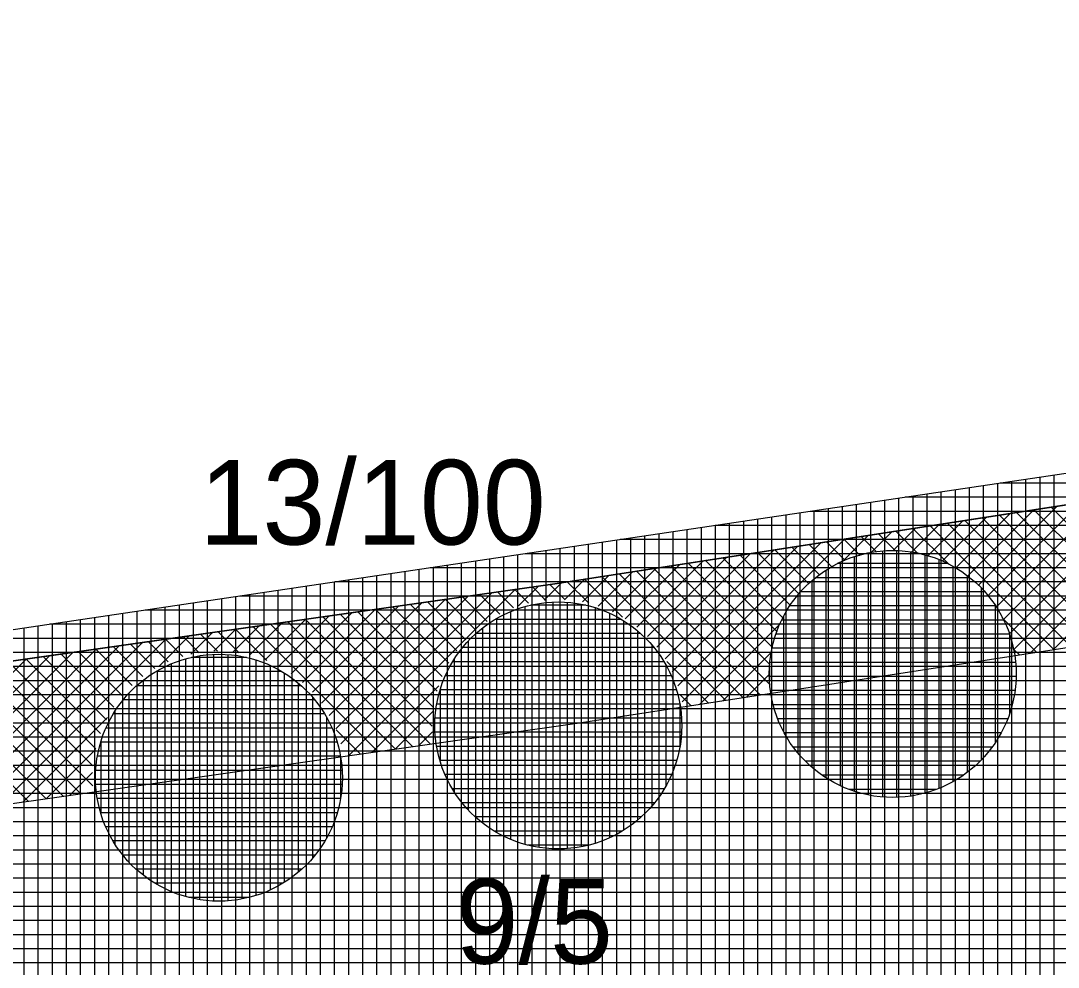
# Model space of a CAD drawing. Extents: x -565346 to -564154, y -1097386 to -1095620.
# Drawn here: x -564969.31 to -564954.61, y -1095806.24 to -1095792.83 of the extents above; entities that cross this region are included whole.
import ezdxf

# ---------------------------------------------------------------- set-up
doc = ezdxf.new("R2010")
doc.units = 0
for name, color, linetype in [('Vrstva 13', 7, 'Continuous'), ('Vrstva 40', 7, 'Continuous'), ('Vrstva 41', 7, 'Continuous'), ('Vrstva 42', 7, 'Continuous'), ('Vrstva 43', 7, 'Continuous'), ('Vrstva 44', 7, 'Continuous')]:
    doc.layers.add(name, color=color, linetype=linetype)

msp = doc.modelspace()

# ---------------------------------------------------------------- linework, layer by layer
at = {"layer": 'Vrstva 13'}
for p, q in [((-564961.71, -1095800.8), (-564879.81, -1095788.15)), ((-565039.47, -1095811.86), (-564961.71, -1095800.8))]:
    msp.add_line(p, q, dxfattribs=at)
at = {"layer": 'Vrstva 41'}
for p, q in [((-564955.303, -1095801.518), (-564953.283, -1095799.498)), ((-564955.243, -1095801.741), (-564952.948, -1095799.447)), ((-564955.608, -1095800.975), (-564954.286, -1095799.653)), ((-564955.489, -1095801.139), (-564953.952, -1095799.602)), ((-564955.387, -1095801.319), (-564953.617, -1095799.55)), ((-564956.064, -1095800.583), (-564955.29, -1095799.808)), ((-564955.896, -1095800.697), (-564954.955, -1095799.757)), ((-564955.744, -1095800.828), (-564954.621, -1095799.705)), ((-564953.995, -1095800.997), (-564955.197, -1095799.794)), ((-564953.933, -1095800.776), (-564954.952, -1095799.756)), ((-564953.849, -1095800.576), (-564954.707, -1095799.718)), ((-564956.691, -1095800.361), (-564956.293, -1095799.963)), ((-564956.458, -1095800.411), (-564955.959, -1095799.912)), ((-564956.251, -1095800.486), (-564955.624, -1095799.86)), ((-564954.424, -1095801.698), (-564956.177, -1095799.945)), ((-564954.179, -1095801.661), (-564955.932, -1095799.908)), ((-564954.022, -1095801.535), (-564955.687, -1095799.87)), ((-564954.026, -1095801.248), (-564955.442, -1095799.832)), ((-564957.671, -1095800.493), (-564957.297, -1095800.118)), ((-564957.263, -1095800.368), (-564956.962, -1095800.067)), ((-564956.914, -1095800.34), (-564957.157, -1095800.097)), ((-564956.951, -1095800.338), (-564956.628, -1095800.015)), ((-564956.596, -1095800.375), (-564956.912, -1095800.059)), ((-564956.153, -1095800.535), (-564956.667, -1095800.021)), ((-564954.669, -1095801.736), (-564956.422, -1095799.983)), ((-564959.998, -1095802.254), (-564957.966, -1095800.222)), ((-564959.94, -1095802.479), (-564957.631, -1095800.17)), ((-564957.818, -1095800.567), (-564958.137, -1095800.248)), ((-564957.628, -1095800.475), (-564957.892, -1095800.21)), ((-564957.417, -1095800.403), (-564957.647, -1095800.172)), ((-564957.182, -1095800.355), (-564957.402, -1095800.135)), ((-564960.297, -1095801.704), (-564958.97, -1095800.377)), ((-564960.18, -1095801.87), (-564958.635, -1095800.325)), ((-564960.08, -1095802.053), (-564958.3, -1095800.273)), ((-564958.403, -1095801.114), (-564959.117, -1095800.4)), ((-564958.281, -1095800.952), (-564958.872, -1095800.362)), ((-564958.144, -1095800.808), (-564958.627, -1095800.324)), ((-564957.99, -1095800.679), (-564958.382, -1095800.286)), ((-564960.745, -1095801.303), (-564959.973, -1095800.532)), ((-564960.579, -1095801.421), (-564959.639, -1095800.48)), ((-564960.43, -1095801.554), (-564959.304, -1095800.428)), ((-564958.693, -1095801.955), (-564960.097, -1095800.551)), ((-564958.658, -1095801.707), (-564959.852, -1095800.513)), ((-564958.594, -1095801.489), (-564959.607, -1095800.475)), ((-564958.507, -1095801.292), (-564959.362, -1095800.437)), ((-564961.351, -1095801.061), (-564960.977, -1095800.687)), ((-564961.128, -1095801.121), (-564960.642, -1095800.635)), ((-564959.324, -1095802.455), (-564961.077, -1095800.702)), ((-564960.927, -1095801.203), (-564960.308, -1095800.583)), ((-564959.079, -1095802.417), (-564960.832, -1095800.664)), ((-564958.834, -1095802.379), (-564960.587, -1095800.627)), ((-564958.692, -1095802.239), (-564960.342, -1095800.589)), ((-564955.007, -1095801.788), (-564953.895, -1095800.676)), ((-564962.258, -1095801.12), (-564961.976, -1095800.838)), ((-564961.874, -1095801.037), (-564962.061, -1095800.85)), ((-564961.895, -1095801.039), (-564961.646, -1095800.79)), ((-564961.596, -1095801.032), (-564961.813, -1095800.815)), ((-564961.604, -1095801.032), (-564961.311, -1095800.738)), ((-564961.263, -1095801.082), (-564961.567, -1095800.778)), ((-564960.785, -1095801.277), (-564961.322, -1095800.74)), ((-564964.849, -1095802.862), (-564962.965, -1095800.979)), ((-564964.777, -1095803.073), (-564962.636, -1095800.932)), ((-564964.661, -1095803.24), (-564962.306, -1095800.885)), ((-564962.702, -1095801.341), (-564963.051, -1095800.991)), ((-564962.524, -1095801.235), (-564962.804, -1095800.956)), ((-564962.33, -1095801.147), (-564962.556, -1095800.92)), ((-564962.115, -1095801.079), (-564962.309, -1095800.885)), ((-564965.179, -1095802.344), (-564963.955, -1095801.119)), ((-564965.051, -1095802.499), (-564963.625, -1095801.072)), ((-564964.941, -1095802.671), (-564963.295, -1095801.025)), ((-564963.245, -1095801.929), (-564964.042, -1095801.132)), ((-564963.134, -1095801.757), (-564963.794, -1095801.096)), ((-564963.006, -1095801.602), (-564963.547, -1095801.061)), ((-564962.862, -1095801.463), (-564963.299, -1095801.026)), ((-564954.673, -1095801.737), (-564954.006, -1095801.07)), ((-564965.657, -1095801.973), (-564964.944, -1095801.26)), ((-564965.481, -1095802.08), (-564964.614, -1095801.213)), ((-564965.322, -1095802.204), (-564964.284, -1095801.166)), ((-564963.48, -1095802.825), (-564965.032, -1095801.273)), ((-564963.461, -1095802.561), (-564964.785, -1095801.237)), ((-564963.411, -1095802.328), (-564964.537, -1095801.202)), ((-564963.338, -1095802.118), (-564964.29, -1095801.167)), ((-564954.914, -1095801.774), (-564955.405, -1095801.283)), ((-564966.578, -1095801.763), (-564966.263, -1095801.448)), ((-564966.303, -1095801.77), (-564965.933, -1095801.401)), ((-564966.065, -1095801.815), (-564965.603, -1095801.354)), ((-564964.254, -1095803.182), (-564966.023, -1095801.413)), ((-564965.851, -1095801.884), (-564965.274, -1095801.307)), ((-564964.007, -1095803.147), (-564965.775, -1095801.378)), ((-564963.759, -1095803.112), (-564965.528, -1095801.343)), ((-564963.511, -1095803.076), (-564965.28, -1095801.308)), ((-564959.69, -1095802.512), (-564958.545, -1095801.367)), ((-564969.607, -1095803.943), (-564967.252, -1095801.588)), ((-564967.358, -1095801.976), (-564966.922, -1095801.541)), ((-564967.016, -1095801.835), (-564967.261, -1095801.59)), ((-564966.785, -1095801.783), (-564967.013, -1095801.554)), ((-564966.903, -1095801.805), (-564966.593, -1095801.494)), ((-564966.525, -1095801.76), (-564966.766, -1095801.519)), ((-564966.218, -1095801.784), (-564966.518, -1095801.484)), ((-564965.825, -1095801.894), (-564966.271, -1095801.449)), ((-564969.908, -1095803.396), (-564968.241, -1095801.729)), ((-564969.82, -1095803.59), (-564967.912, -1095801.682)), ((-564969.752, -1095803.806), (-564967.582, -1095801.635)), ((-564967.733, -1095802.248), (-564968.252, -1095801.73)), ((-564967.581, -1095802.119), (-564968.004, -1095801.695)), ((-564967.411, -1095802.005), (-564967.756, -1095801.66)), ((-564967.223, -1095801.91), (-564967.509, -1095801.625)), ((-564955.159, -1095801.812), (-564955.245, -1095801.726)), ((-564970.279, -1095802.918), (-564969.231, -1095801.87)), ((-564970.139, -1095803.061), (-564968.901, -1095801.823)), ((-564970.015, -1095803.22), (-564968.571, -1095801.776)), ((-564968.185, -1095802.929), (-564969.242, -1095801.871)), ((-564968.098, -1095802.733), (-564968.994, -1095801.836)), ((-564967.993, -1095802.555), (-564968.747, -1095801.801)), ((-564967.871, -1095802.394), (-564968.499, -1095801.766)), ((-564959.356, -1095802.46), (-564958.67, -1095801.775)), ((-564968.464, -1095803.781), (-564970.232, -1095802.012)), ((-564968.294, -1095803.668), (-564969.985, -1095801.977)), ((-564968.291, -1095803.388), (-564969.737, -1095801.942)), ((-564968.251, -1095803.146), (-564969.49, -1095801.907)), ((-564959.569, -1095802.493), (-564960.157, -1095801.905)), ((-564969.207, -1095803.886), (-564970.975, -1095802.118)), ((-564968.959, -1095803.851), (-564970.728, -1095802.083)), ((-564968.712, -1095803.816), (-564970.48, -1095802.047)), ((-564959.021, -1095802.408), (-564958.7, -1095802.087)), ((-564964.331, -1095803.193), (-564963.388, -1095802.25)), ((-564959.814, -1095802.531), (-564959.962, -1095802.383)), ((-564958.687, -1095802.357), (-564958.677, -1095802.347)), ((-564964.002, -1095803.146), (-564963.469, -1095802.613)), ((-564969.278, -1095803.896), (-564968.082, -1095802.7)), ((-564964.502, -1095803.217), (-564964.844, -1095802.875)), ((-564963.672, -1095803.099), (-564963.476, -1095802.904)), ((-564968.948, -1095803.85), (-564968.253, -1095803.155)), ((-564968.618, -1095803.803), (-564968.295, -1095803.48)), ((-564968.288, -1095803.756), (-564968.288, -1095803.755))]:
    msp.add_line(p, q, dxfattribs=at)
at = {"layer": 'Vrstva 42'}
msp.add_lwpolyline([(-565024.871, -1095809.784), (-565024.921, -1095811.811), (-564961.428, -1095802.78), (-564933.86, -1095798.523), (-564934.165, -1095796.546), (-564961.71, -1095800.8)], close=True, dxfattribs=at)
at = {"layer": 'Vrstva 43'}
for p, q in [((-564955.47, -1095799.386), (-564955.47, -1095814.547)), ((-564858.814, -1095799.38), (-564955.431, -1095799.38)), ((-564955.27, -1095799.356), (-564955.27, -1095814.518)), ((-564955.07, -1095799.326), (-564955.07, -1095814.488)), ((-564954.87, -1095799.297), (-564954.87, -1095814.458)), ((-564954.67, -1095799.267), (-564954.67, -1095814.429)), ((-564956.47, -1095799.534), (-564956.47, -1095814.696)), ((-564956.27, -1095799.505), (-564956.27, -1095814.666)), ((-564956.07, -1095799.475), (-564956.07, -1095814.637)), ((-564955.87, -1095799.445), (-564955.87, -1095814.607)), ((-564955.67, -1095799.415), (-564955.67, -1095814.577)), ((-564957.47, -1095799.683), (-564957.47, -1095814.845)), ((-564957.27, -1095799.653), (-564957.27, -1095814.815)), ((-564957.07, -1095799.623), (-564957.07, -1095814.785)), ((-564956.87, -1095799.594), (-564956.87, -1095814.755)), ((-564859.856, -1095799.58), (-564956.778, -1095799.58)), ((-564956.67, -1095799.564), (-564956.67, -1095814.726)), ((-564958.27, -1095799.802), (-564958.27, -1095814.963)), ((-564860.898, -1095799.78), (-564958.125, -1095799.78)), ((-564958.07, -1095799.772), (-564958.07, -1095814.934)), ((-564957.87, -1095799.742), (-564957.87, -1095814.904)), ((-564957.67, -1095799.712), (-564957.67, -1095814.874)), ((-564959.27, -1095799.95), (-564959.27, -1095815.112)), ((-564959.07, -1095799.92), (-564959.07, -1095815.082)), ((-564958.87, -1095799.891), (-564958.87, -1095815.052)), ((-564958.67, -1095799.861), (-564958.67, -1095815.023)), ((-564958.47, -1095799.831), (-564958.47, -1095814.993)), ((-564960.27, -1095800.099), (-564960.27, -1095815.26)), ((-564960.07, -1095800.069), (-564960.07, -1095815.231)), ((-564959.87, -1095800.039), (-564959.87, -1095815.201)), ((-564959.67, -1095800.009), (-564959.67, -1095815.171)), ((-564861.94, -1095799.98), (-564959.472, -1095799.98)), ((-564959.47, -1095799.98), (-564959.47, -1095815.142)), ((-564961.27, -1095800.247), (-564961.27, -1095815.409)), ((-564961.07, -1095800.217), (-564961.07, -1095815.379)), ((-564960.87, -1095800.188), (-564960.87, -1095815.349)), ((-564862.982, -1095800.18), (-564960.818, -1095800.18)), ((-564960.67, -1095800.158), (-564960.67, -1095815.32)), ((-564960.47, -1095800.128), (-564960.47, -1095815.29)), ((-564962.27, -1095800.396), (-564962.27, -1095815.557)), ((-564864.024, -1095800.38), (-564962.165, -1095800.38)), ((-564962.07, -1095800.366), (-564962.07, -1095815.528)), ((-564961.87, -1095800.336), (-564961.87, -1095815.498)), ((-564961.67, -1095800.306), (-564961.67, -1095815.468)), ((-564961.47, -1095800.277), (-564961.47, -1095815.439)), ((-564963.27, -1095800.544), (-564963.27, -1095815.706)), ((-564963.07, -1095800.514), (-564963.07, -1095815.676)), ((-564962.87, -1095800.485), (-564962.87, -1095815.647)), ((-564962.67, -1095800.455), (-564962.67, -1095815.617)), ((-564962.47, -1095800.425), (-564962.47, -1095815.587)), ((-564964.27, -1095800.693), (-564964.27, -1095815.854)), ((-564964.07, -1095800.663), (-564964.07, -1095815.825)), ((-564963.87, -1095800.633), (-564963.87, -1095815.795)), ((-564963.67, -1095800.603), (-564963.67, -1095815.765)), ((-564865.066, -1095800.58), (-564963.512, -1095800.58)), ((-564963.47, -1095800.574), (-564963.47, -1095815.736)), ((-564965.27, -1095800.841), (-564965.27, -1095816.003)), ((-564965.07, -1095800.811), (-564965.07, -1095815.973)), ((-564964.87, -1095800.782), (-564964.87, -1095815.944)), ((-564866.109, -1095800.78), (-564964.859, -1095800.78)), ((-564964.67, -1095800.752), (-564964.67, -1095815.914)), ((-564964.47, -1095800.722), (-564964.47, -1095815.884)), ((-564966.27, -1095800.99), (-564966.27, -1095816.152)), ((-564867.151, -1095800.98), (-564966.206, -1095800.98)), ((-564966.07, -1095800.96), (-564966.07, -1095816.122)), ((-564965.87, -1095800.93), (-564965.87, -1095816.092)), ((-564965.67, -1095800.9), (-564965.67, -1095816.062)), ((-564965.47, -1095800.871), (-564965.47, -1095816.033)), ((-564967.27, -1095801.138), (-564967.27, -1095816.3)), ((-564967.07, -1095801.108), (-564967.07, -1095816.27)), ((-564966.87, -1095801.079), (-564966.87, -1095816.241)), ((-564966.67, -1095801.049), (-564966.67, -1095816.211)), ((-564966.47, -1095801.019), (-564966.47, -1095816.181)), ((-564968.27, -1095801.287), (-564968.27, -1095816.449)), ((-564968.07, -1095801.257), (-564968.07, -1095816.419)), ((-564967.87, -1095801.227), (-564967.87, -1095816.389)), ((-564967.67, -1095801.197), (-564967.67, -1095816.359)), ((-564868.193, -1095801.18), (-564967.552, -1095801.18)), ((-564967.47, -1095801.168), (-564967.47, -1095816.33)), ((-564969.27, -1095801.435), (-564969.27, -1095816.597)), ((-564969.07, -1095801.405), (-564969.07, -1095816.567)), ((-564869.235, -1095801.38), (-564968.899, -1095801.38)), ((-564968.87, -1095801.376), (-564968.87, -1095816.538)), ((-564968.67, -1095801.346), (-564968.67, -1095816.508)), ((-564968.47, -1095801.316), (-564968.47, -1095816.478)), ((-564870.277, -1095801.58), (-564970.246, -1095801.58)), ((-564871.319, -1095801.78), (-564971.593, -1095801.78)), ((-564872.361, -1095801.98), (-564972.939, -1095801.98)), ((-564873.404, -1095802.18), (-564974.286, -1095802.18)), ((-564874.446, -1095802.38), (-564975.633, -1095802.38)), ((-564875.488, -1095802.58), (-564976.98, -1095802.58)), ((-564876.53, -1095802.78), (-564978.326, -1095802.78)), ((-564877.587, -1095802.98), (-564979.673, -1095802.98)), ((-564878.934, -1095803.18), (-564981.02, -1095803.18)), ((-564880.28, -1095803.38), (-564982.367, -1095803.38)), ((-564881.627, -1095803.58), (-564983.714, -1095803.58)), ((-564882.974, -1095803.78), (-564985.06, -1095803.78)), ((-564884.32, -1095803.98), (-564986.407, -1095803.98)), ((-564885.667, -1095804.18), (-564987.754, -1095804.18)), ((-564887.013, -1095804.38), (-564989.101, -1095804.38)), ((-564888.36, -1095804.58), (-564990.447, -1095804.58)), ((-564889.707, -1095804.78), (-564991.794, -1095804.78)), ((-564891.053, -1095804.98), (-564993.141, -1095804.98)), ((-564892.4, -1095805.18), (-564994.488, -1095805.18)), ((-564893.746, -1095805.38), (-564995.835, -1095805.38)), ((-564895.093, -1095805.58), (-564997.181, -1095805.58)), ((-564896.439, -1095805.78), (-564998.528, -1095805.78)), ((-564897.786, -1095805.98), (-564999.875, -1095805.98)), ((-564899.133, -1095806.18), (-565001.222, -1095806.18))]:
    msp.add_line(p, q, dxfattribs=at)
msp.add_lwpolyline([(-564584.17, -1095730.99), (-564361.01, -1095672.63), (-564329.81, -1095662.26), (-564326.21, -1095642.73), (-564394.52, -1095662.95), (-564454.33, -1095677.56), (-564516.6, -1095690.89), (-564574.04, -1095705.03), (-564590.74, -1095715.12), (-564631.48, -1095731.18), (-564693.31, -1095752.31), (-564772.2, -1095768.91), (-564879.81, -1095788.15), (-565039.47, -1095811.86), (-565040.85, -1095849.94), (-565025.81, -1095848.33), (-565025.24, -1095824.91), (-564877.52, -1095802.97), (-564694, -1095767.75), (-564603.8, -1095739.23), (-564594.74, -1095734.52)], close=True, dxfattribs=at)
at = {"layer": 'Vrstva 44'}
for p, q in [((-564957.3, -1095800.37), (-564957.3, -1095803.798)), ((-564957.1, -1095800.34), (-564957.1, -1095803.826)), ((-564956.9, -1095800.336), (-564956.9, -1095803.831)), ((-564956.7, -1095800.354), (-564956.7, -1095803.814)), ((-564956.5, -1095800.396), (-564956.5, -1095803.774)), ((-564956.173, -1095800.52), (-564957.739, -1095800.52)), ((-564957.7, -1095800.503), (-564957.7, -1095803.665)), ((-564957.5, -1095800.423), (-564957.5, -1095803.745)), ((-564956.3, -1095800.462), (-564956.3, -1095803.705)), ((-564956.1, -1095800.558), (-564956.1, -1095803.609)), ((-564957.9, -1095800.613), (-564957.9, -1095803.556)), ((-564955.9, -1095800.69), (-564955.9, -1095803.48)), ((-564958.1, -1095800.764), (-564958.1, -1095803.404)), ((-564955.859, -1095800.72), (-564958.048, -1095800.72)), ((-564958.3, -1095800.968), (-564958.3, -1095803.201)), ((-564955.65, -1095800.92), (-564958.261, -1095800.92)), ((-564955.7, -1095800.865), (-564955.7, -1095803.302)), ((-564962.17, -1095801.13), (-564962.17, -1095804.497)), ((-564961.302, -1095801.11), (-564962.084, -1095801.11)), ((-564961.97, -1095801.087), (-564961.97, -1095804.54)), ((-564961.77, -1095801.068), (-564961.77, -1095804.561)), ((-564961.57, -1095801.07), (-564961.57, -1095804.559)), ((-564961.37, -1095801.096), (-564961.37, -1095804.532)), ((-564961.17, -1095801.145), (-564961.17, -1095804.482)), ((-564955.495, -1095801.12), (-564958.412, -1095801.12)), ((-564955.5, -1095801.112), (-564955.5, -1095803.054)), ((-564962.37, -1095801.202), (-564962.37, -1095804.427)), ((-564960.97, -1095801.223), (-564960.97, -1095804.406)), ((-564958.5, -1095801.268), (-564958.5, -1095802.9)), ((-564962.77, -1095801.434), (-564962.77, -1095804.194)), ((-564960.803, -1095801.31), (-564962.586, -1095801.31)), ((-564962.57, -1095801.301), (-564962.57, -1095804.327)), ((-564960.77, -1095801.33), (-564960.77, -1095804.299)), ((-564955.382, -1095801.32), (-564958.527, -1095801.32)), ((-564960.53, -1095801.51), (-564962.859, -1095801.51)), ((-564960.57, -1095801.474), (-564960.57, -1095804.153)), ((-564955.299, -1095801.52), (-564958.61, -1095801.52)), ((-564955.3, -1095801.516), (-564955.3, -1095802.65)), ((-564960.338, -1095801.71), (-564963.049, -1095801.71)), ((-564962.97, -1095801.619), (-564962.97, -1095804.009)), ((-564960.37, -1095801.672), (-564960.37, -1095803.956)), ((-564955.243, -1095801.72), (-564958.664, -1095801.72)), ((-564966.98, -1095801.87), (-564966.98, -1095805.237)), ((-564966.112, -1095801.85), (-564966.894, -1095801.85)), ((-564966.78, -1095801.827), (-564966.78, -1095805.28)), ((-564966.58, -1095801.808), (-564966.58, -1095805.301)), ((-564966.38, -1095801.81), (-564966.38, -1095805.299)), ((-564966.18, -1095801.836), (-564966.18, -1095805.272)), ((-564965.98, -1095801.885), (-564965.98, -1095805.222)), ((-564963.17, -1095801.877), (-564963.17, -1095803.751)), ((-564967.18, -1095801.942), (-564967.18, -1095805.167)), ((-564965.78, -1095801.963), (-564965.78, -1095805.146)), ((-564960.198, -1095801.91), (-564963.192, -1095801.91)), ((-564960.17, -1095801.955), (-564960.17, -1095803.67)), ((-564958.7, -1095801.973), (-564958.7, -1095802.186)), ((-564955.214, -1095801.92), (-564958.695, -1095801.92)), ((-564967.58, -1095802.174), (-564967.58, -1095804.934)), ((-564965.613, -1095802.05), (-564967.396, -1095802.05)), ((-564967.38, -1095802.041), (-564967.38, -1095805.067)), ((-564965.58, -1095802.07), (-564965.58, -1095805.039)), ((-564960.092, -1095802.11), (-564963.295, -1095802.11)), ((-564955.207, -1095802.12), (-564958.702, -1095802.12)), ((-564965.34, -1095802.25), (-564967.669, -1095802.25)), ((-564965.38, -1095802.214), (-564965.38, -1095804.893)), ((-564963.37, -1095802.317), (-564963.37, -1095803.311)), ((-564960.02, -1095802.31), (-564963.368, -1095802.31)), ((-564955.222, -1095802.32), (-564958.688, -1095802.32)), ((-564965.148, -1095802.45), (-564967.859, -1095802.45)), ((-564967.78, -1095802.359), (-564967.78, -1095804.749)), ((-564965.18, -1095802.412), (-564965.18, -1095804.696)), ((-564967.98, -1095802.617), (-564967.98, -1095804.491)), ((-564959.973, -1095802.51), (-564963.416, -1095802.51)), ((-564959.97, -1095802.526), (-564959.97, -1095803.111)), ((-564955.26, -1095802.52), (-564958.648, -1095802.52)), ((-564965.008, -1095802.65), (-564968.002, -1095802.65)), ((-564964.98, -1095802.695), (-564964.98, -1095804.41)), ((-564959.949, -1095802.71), (-564963.441, -1095802.71)), ((-564955.325, -1095802.72), (-564958.582, -1095802.72)), ((-564964.902, -1095802.85), (-564968.105, -1095802.85)), ((-564959.948, -1095802.91), (-564963.441, -1095802.91)), ((-564968.18, -1095803.057), (-564968.18, -1095804.051)), ((-564964.83, -1095803.05), (-564968.178, -1095803.05)), ((-564955.419, -1095802.92), (-564958.49, -1095802.92)), ((-564959.97, -1095803.11), (-564963.417, -1095803.11)), ((-564955.545, -1095803.12), (-564958.363, -1095803.12)), ((-564964.783, -1095803.25), (-564968.226, -1095803.25)), ((-564964.78, -1095803.266), (-564964.78, -1095803.851)), ((-564960.018, -1095803.31), (-564963.37, -1095803.31)), ((-564955.718, -1095803.32), (-564958.191, -1095803.32)), ((-564964.759, -1095803.45), (-564968.251, -1095803.45)), ((-564964.758, -1095803.65), (-564968.251, -1095803.65)), ((-564960.091, -1095803.51), (-564963.299, -1095803.51)), ((-564955.957, -1095803.52), (-564957.951, -1095803.52)), ((-564960.192, -1095803.71), (-564963.196, -1095803.71)), ((-564956.335, -1095803.72), (-564957.572, -1095803.72)), ((-564964.78, -1095803.85), (-564968.227, -1095803.85)), ((-564960.332, -1095803.91), (-564963.056, -1095803.91)), ((-564964.828, -1095804.05), (-564968.18, -1095804.05)), ((-564960.518, -1095804.11), (-564962.868, -1095804.11)), ((-564964.901, -1095804.25), (-564968.109, -1095804.25)), ((-564960.786, -1095804.31), (-564962.599, -1095804.31)), ((-564965.002, -1095804.45), (-564968.006, -1095804.45)), ((-564961.266, -1095804.51), (-564962.122, -1095804.51)), ((-564965.142, -1095804.65), (-564967.866, -1095804.65)), ((-564965.328, -1095804.85), (-564967.678, -1095804.85)), ((-564965.596, -1095805.05), (-564967.409, -1095805.05)), ((-564966.076, -1095805.25), (-564966.932, -1095805.25))]:
    msp.add_line(p, q, dxfattribs=at)
for centre in [(-564956.954, -1095802.084), (-564961.694, -1095802.814), (-564966.504, -1095803.554)]:
    msp.add_circle(centre, 1.75, dxfattribs=at)

# ---------------------------------------------------------------- texts
at = {"layer": 'Vrstva 40'}
for s, p in [('13/100', (-564966.78, -1095800.25)), ('9/5', (-564963.15, -1095806.19))]:
    msp.add_text(s, height=1.2, dxfattribs=at).set_placement(p)

doc.saveas('drawing.dxf')
